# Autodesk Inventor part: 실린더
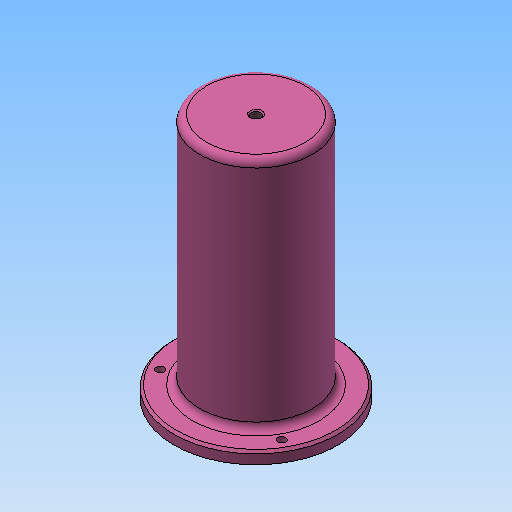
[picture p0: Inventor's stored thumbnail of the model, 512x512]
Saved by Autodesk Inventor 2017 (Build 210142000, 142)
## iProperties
Created: 2017-05
Part Number: 실린더
Material: 알루미늄 6061
Document SubType Name: Modeling
Designer: mduedu
Density: 2.71 g/cm^3
Mass: 201.817 g
Surface Area: 358.986 cm^2
Volume: 74.4712 cm^3
Appearance: 분홍색
Author: mduedu
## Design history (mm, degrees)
sketch "스케치1"
  geometry: C1 r 35 at (0, 0); 1 further point
  constraints: 1 centre point, 1 coincident
  dimensions: "d0" = 70 diameter of C1
extrude "돌출1" new body sketch "스케치1" distance "d1" = 5; taper "d2" = 0 deg
sketch "스케치2"
  geometry: C1 r 24 at (0, 0); 1 further point
  constraints: 1 centre point, 1 coincident
  dimensions: "d3" = 48 diameter of C1
extrude "돌출2" join sketch "스케치2" distance "d4" = 100; taper "d5" = 0 deg
sketch "스케치3"
  geometry: C1 r 20 at (0, 0); 1 further point
  constraints: 1 centre point, 1 coincident
  dimensions: "d6" = 40 diameter of C1
extrude "돌출3" cut sketch "스케치3" distance "d7" = 100; taper "d8" = 0 deg
chamfer "모따기1" distance "d9" = 1; stored, may be unused: second distance "d10" = 2, angle "d11" = 45 deg
fillet "모깎기1" dims "d12" = 3
sketch "스케치5" dims "d16" = 60
  geometry: C1 r 35 at (0, 0) reference; 5 further points
  constraints: 2 vertical alignment, 1 coincident, 6 other
  dimensions: "d20" = 360 deg dimension on point (0, 0) point (0, 30) (derived)
sketch "스케치6"
  geometry: 3 further points
  constraints: 3 other
hole "구멍1" sketch "스케치6" at (-25.981, -15), (25.981, -15), (0, 30) diameter "d22" = 3.4; stored, may be unused: countersink angle "d26" = 90 deg, drill point angle "d28" = 0 deg; dims "d23" = 6, "d24" = 4, "d25" = 2, "d27" = 8
hole "구멍3" diameter "d34" = 4.134; stored, may be unused: countersink angle "d38" = 90 deg, drill point angle "d40" = 118 deg; dims "d32" = 10, "d33" = 10, "d35" = 6, "d36" = 4, "d37" = 2, "d39" = 8
chamfer "모따기2" distance "d41" = 0.5; stored, may be unused: second distance "d42" = 2, angle "d43" = 45 deg
node "솔리드1"
